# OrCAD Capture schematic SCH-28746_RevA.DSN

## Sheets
1 TITLE PAGE: title: USB-KW019032; rev: A; company: Freescale Semiconductor; note: SCH-28746 PDF: SPF-28746; note: 6501 William Cannon Drive West; note: Austin, TX 78735-8598
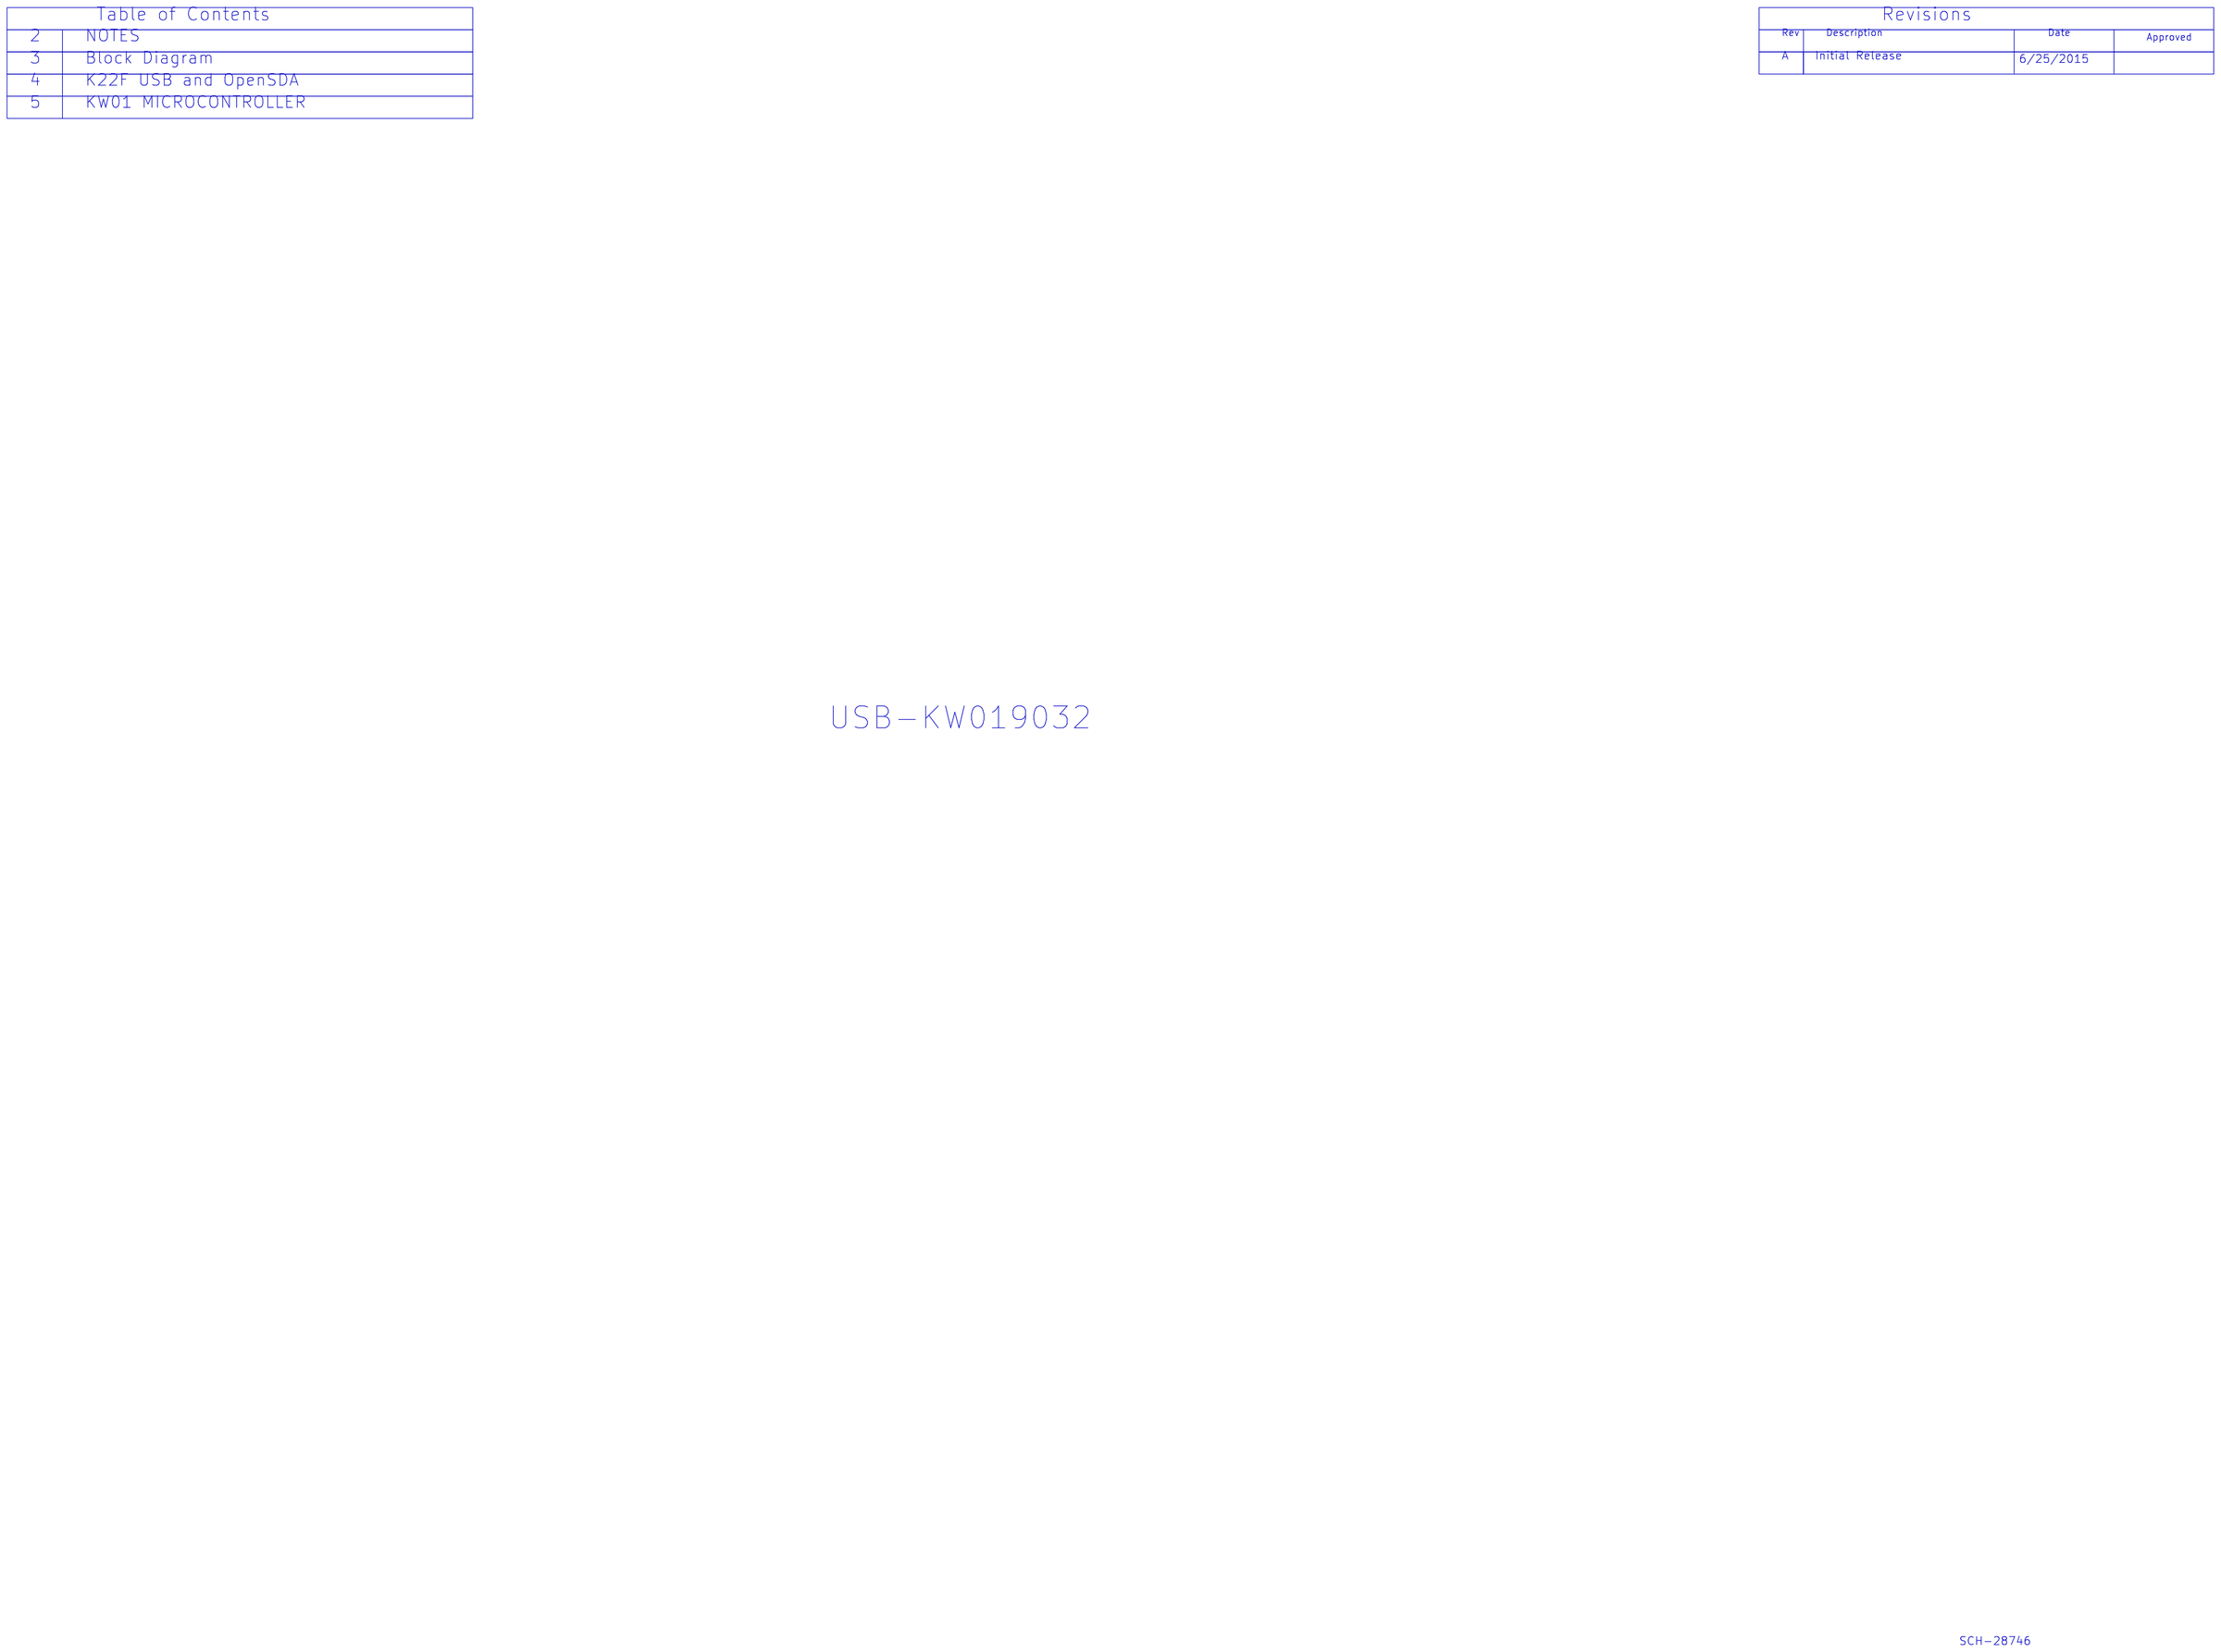
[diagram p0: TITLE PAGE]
2 NOTES
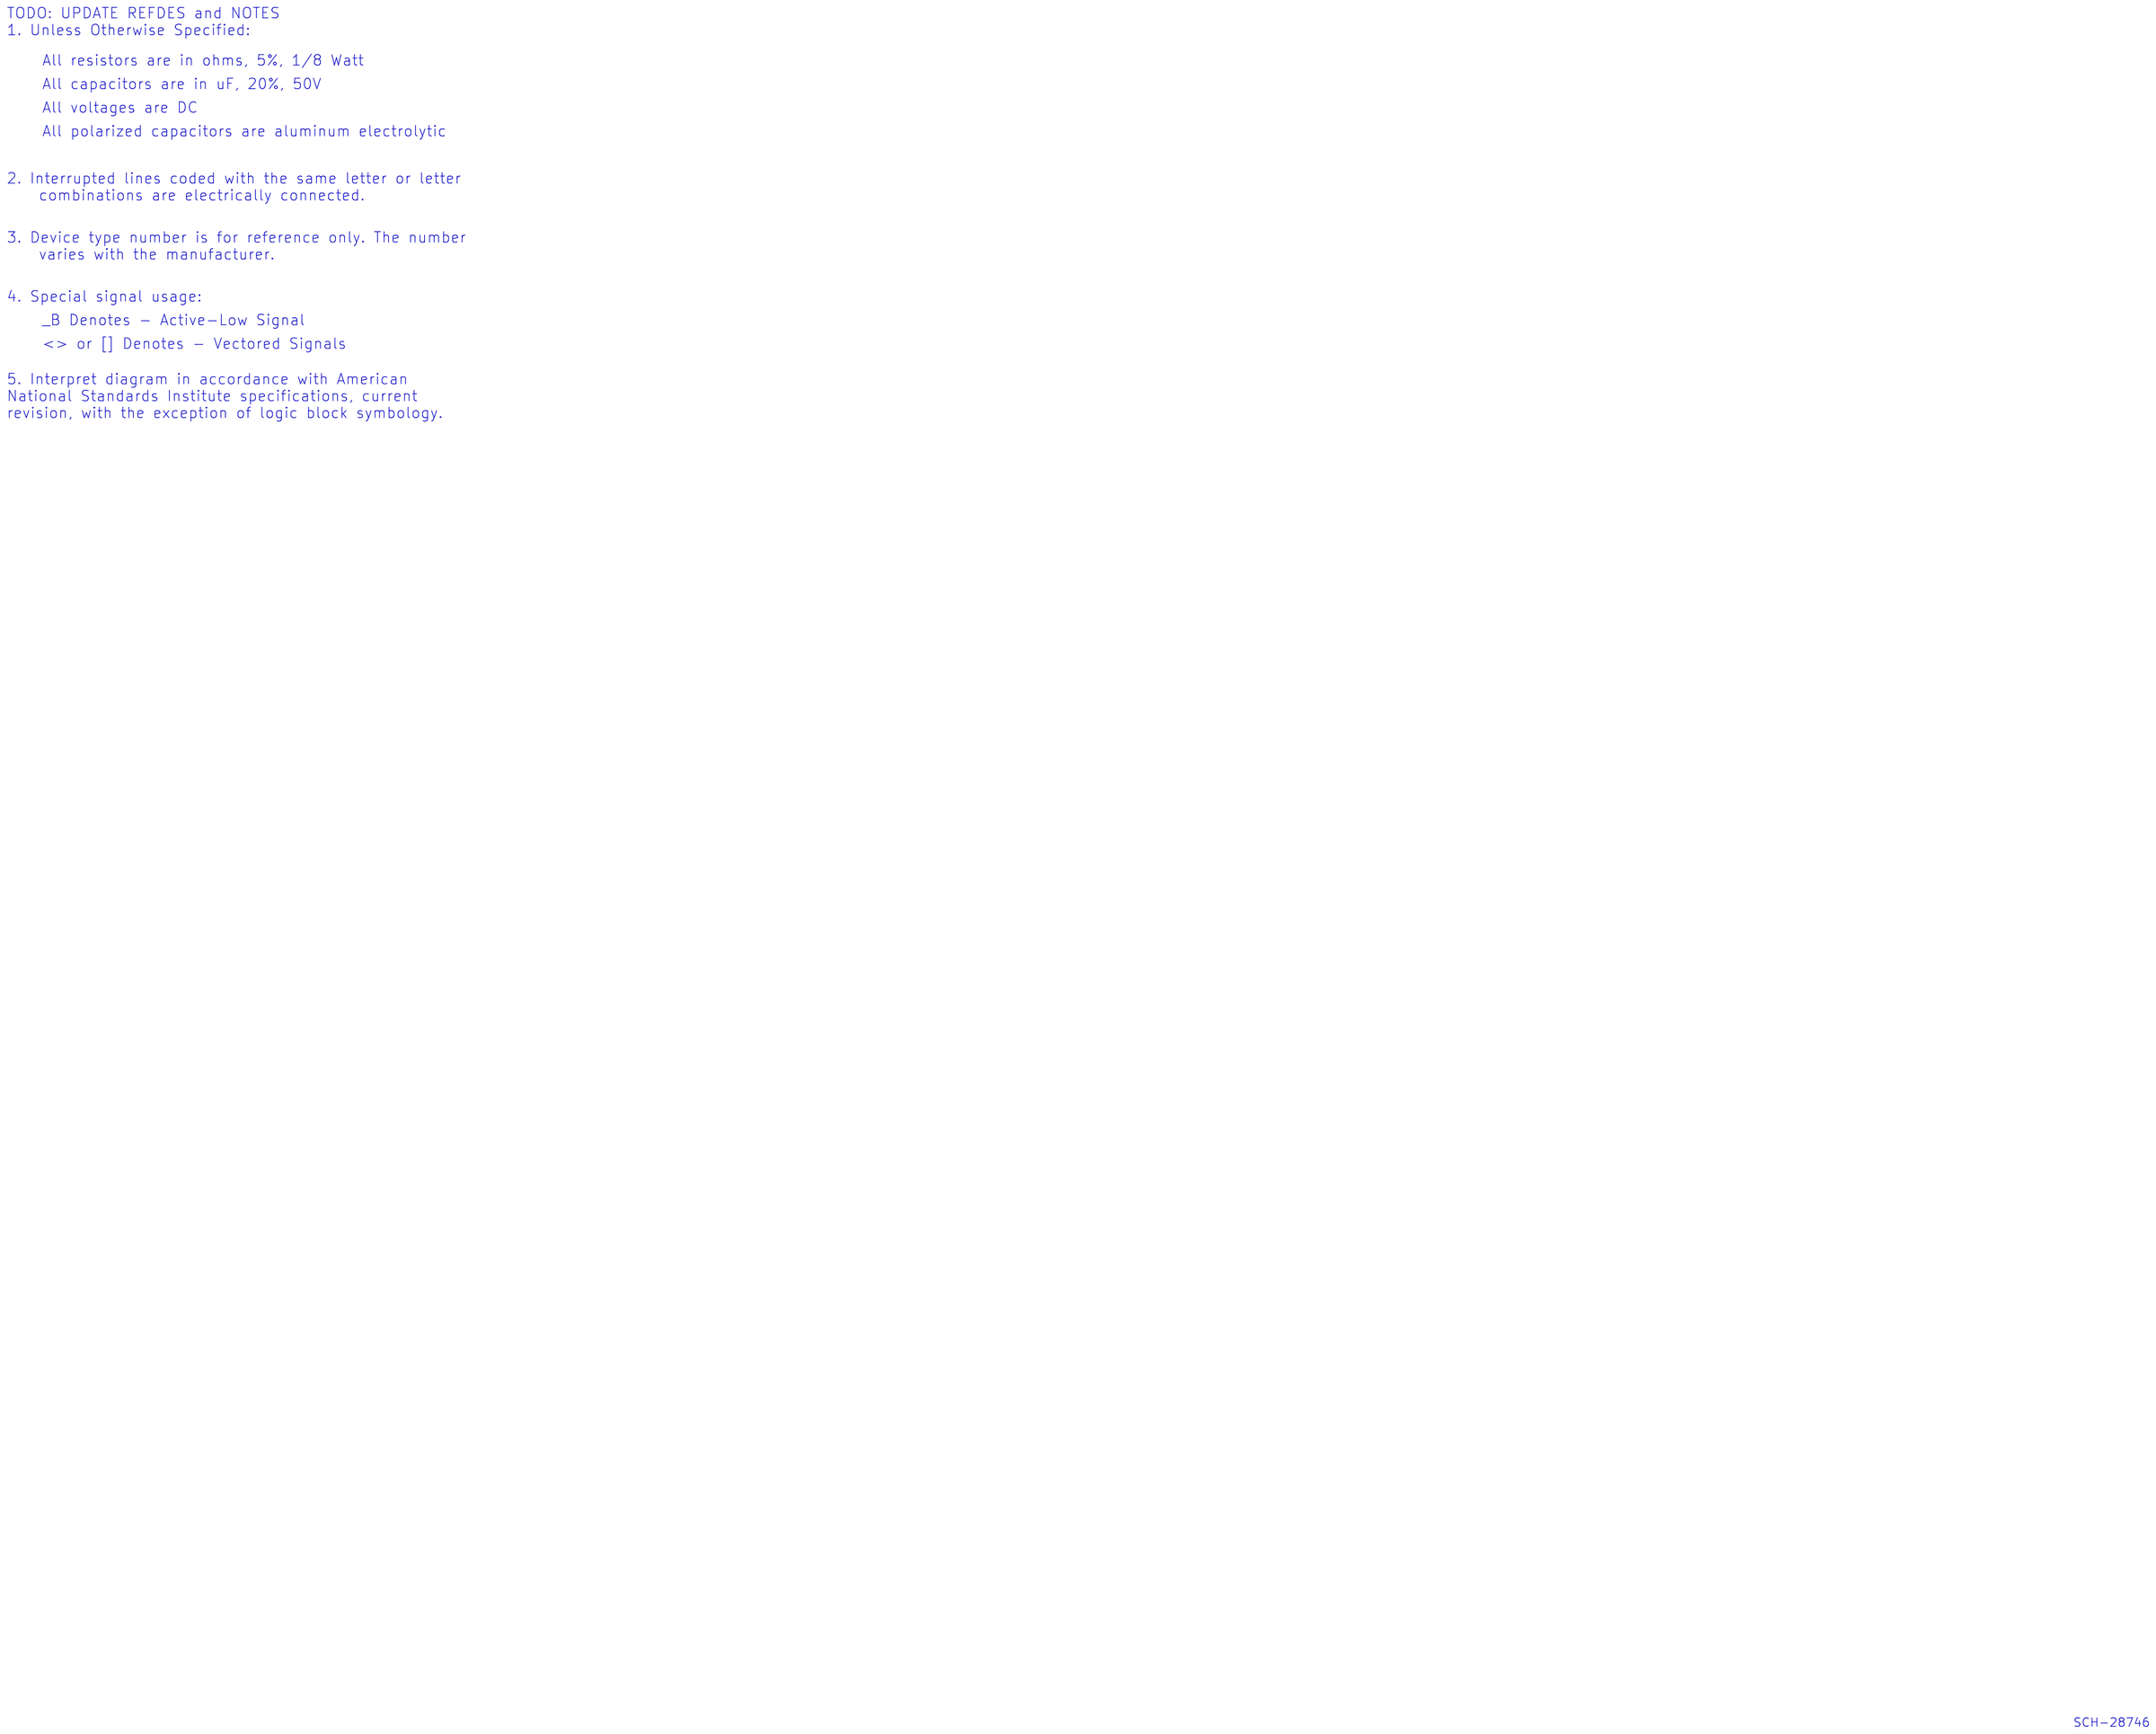
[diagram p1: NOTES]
3 BLOCK DIAGRAM
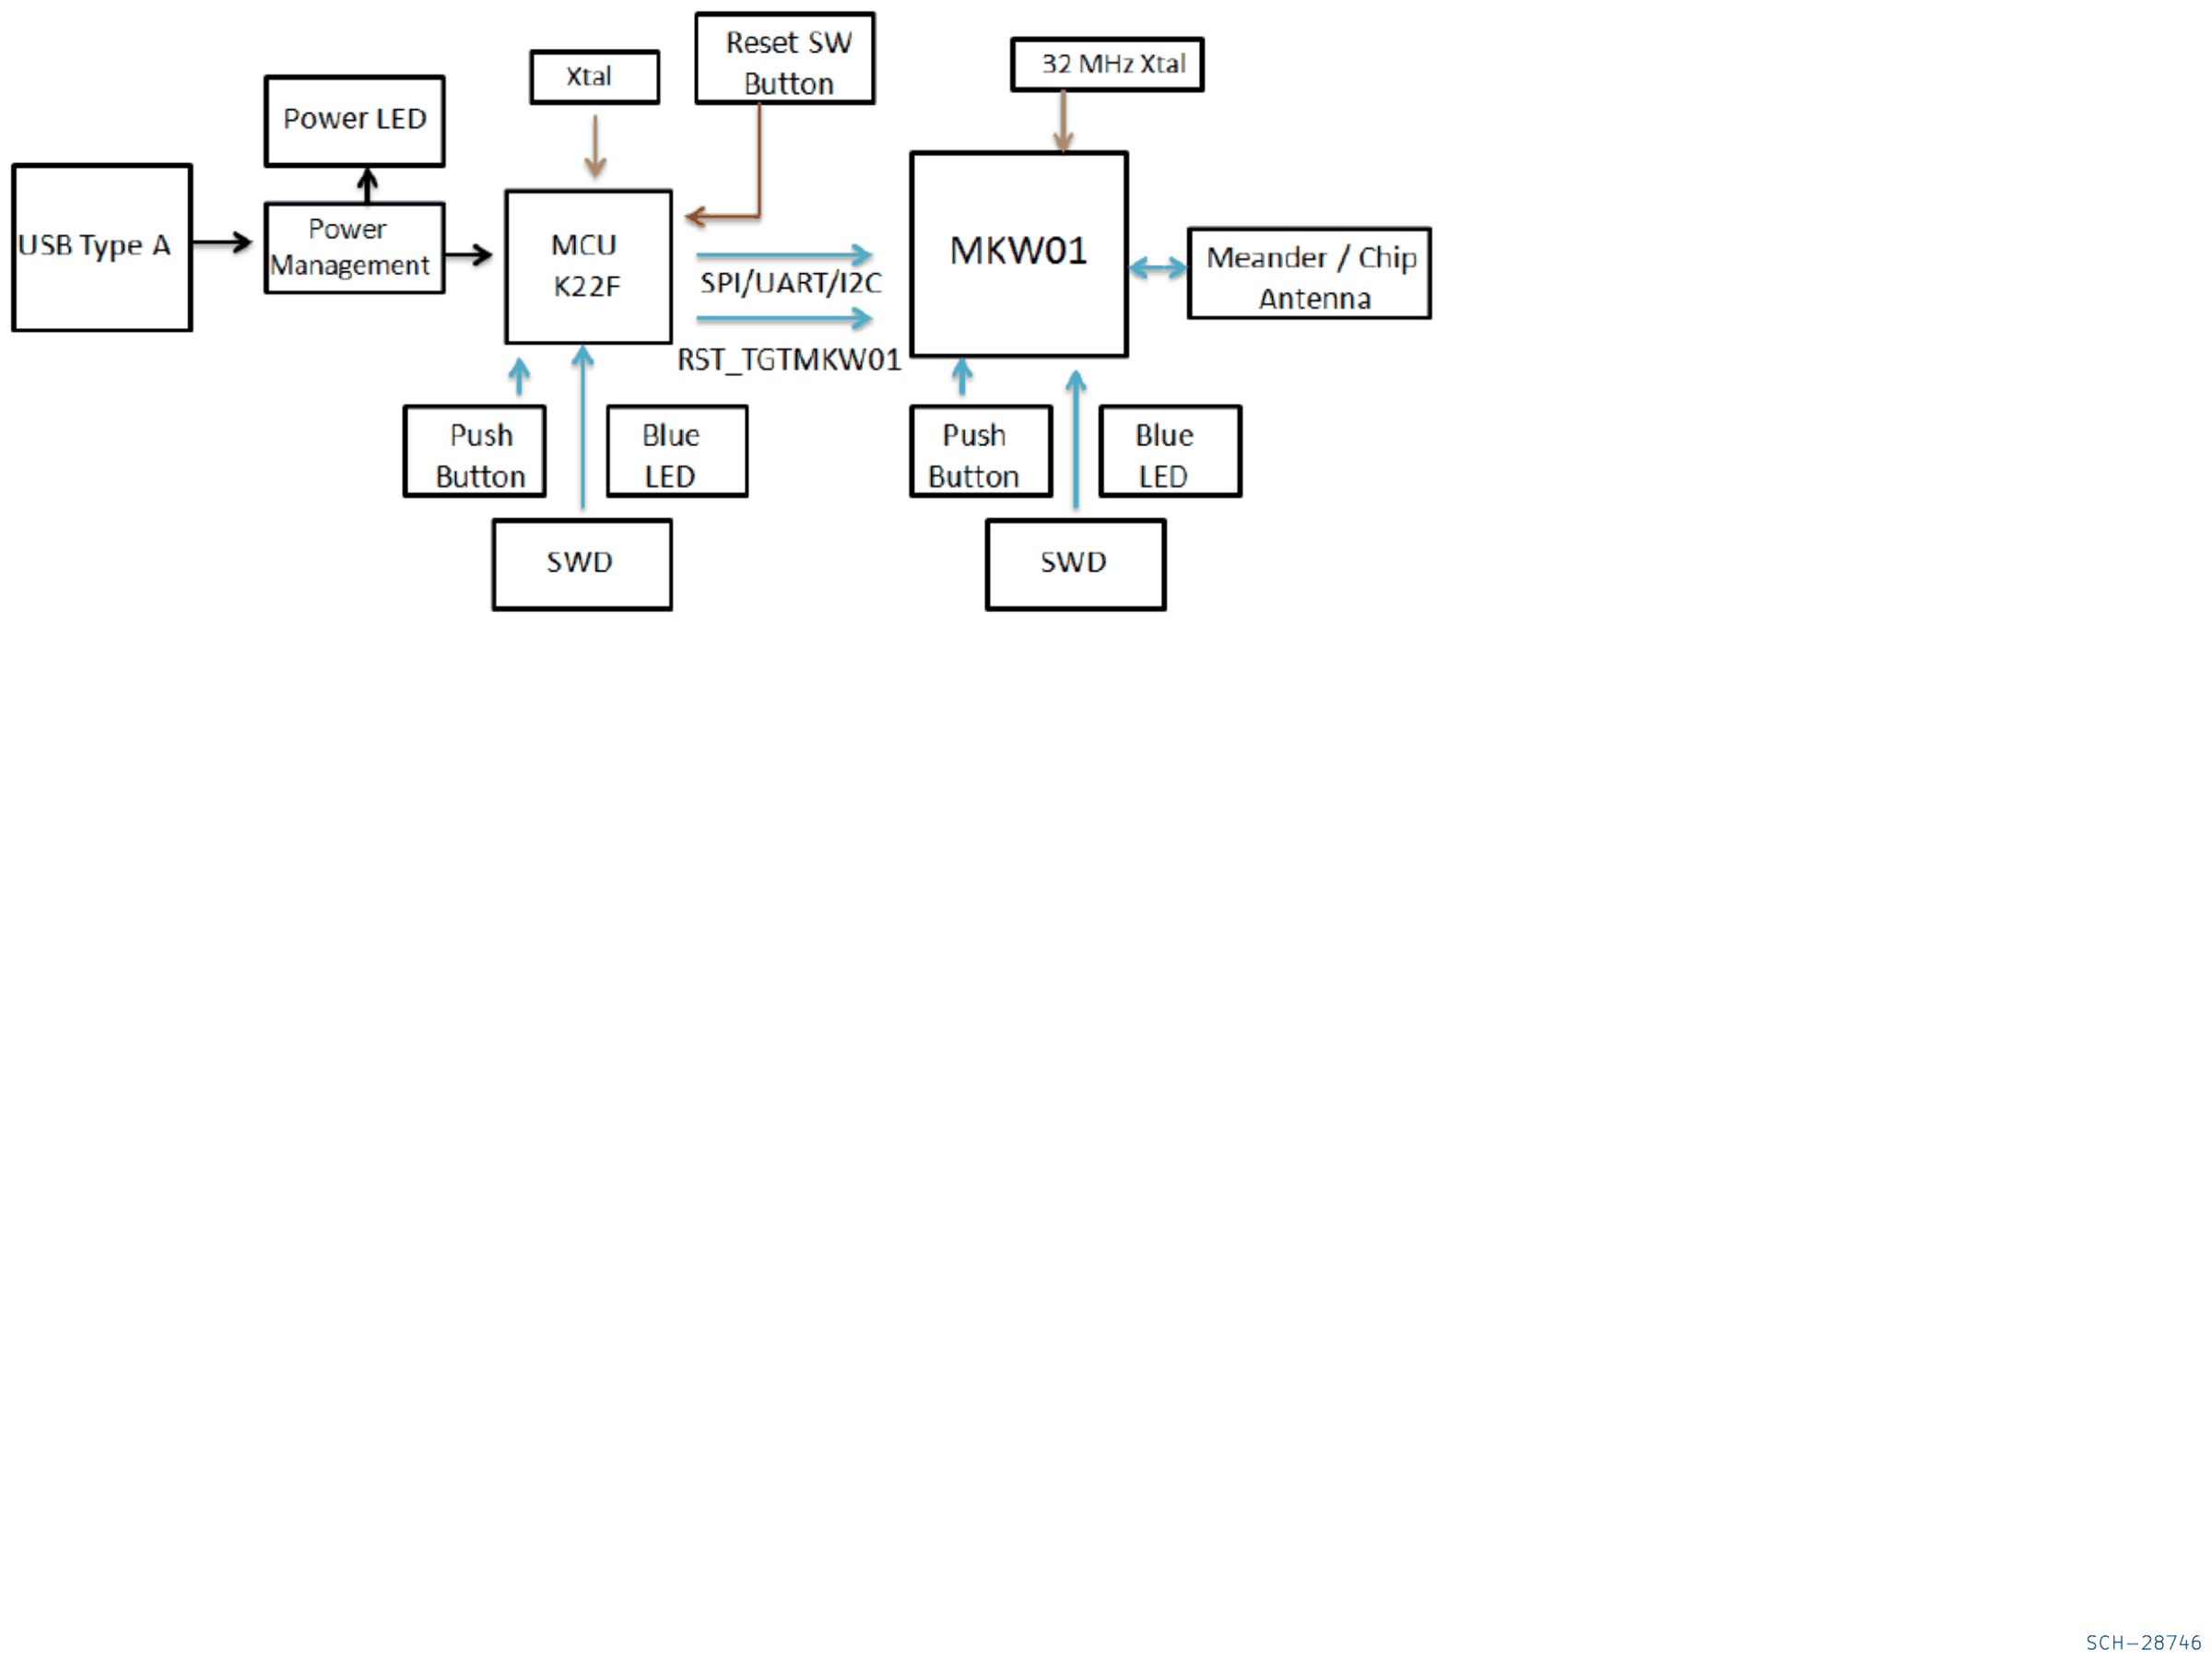
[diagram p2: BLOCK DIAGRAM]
4 USB and OpenSDA: size C
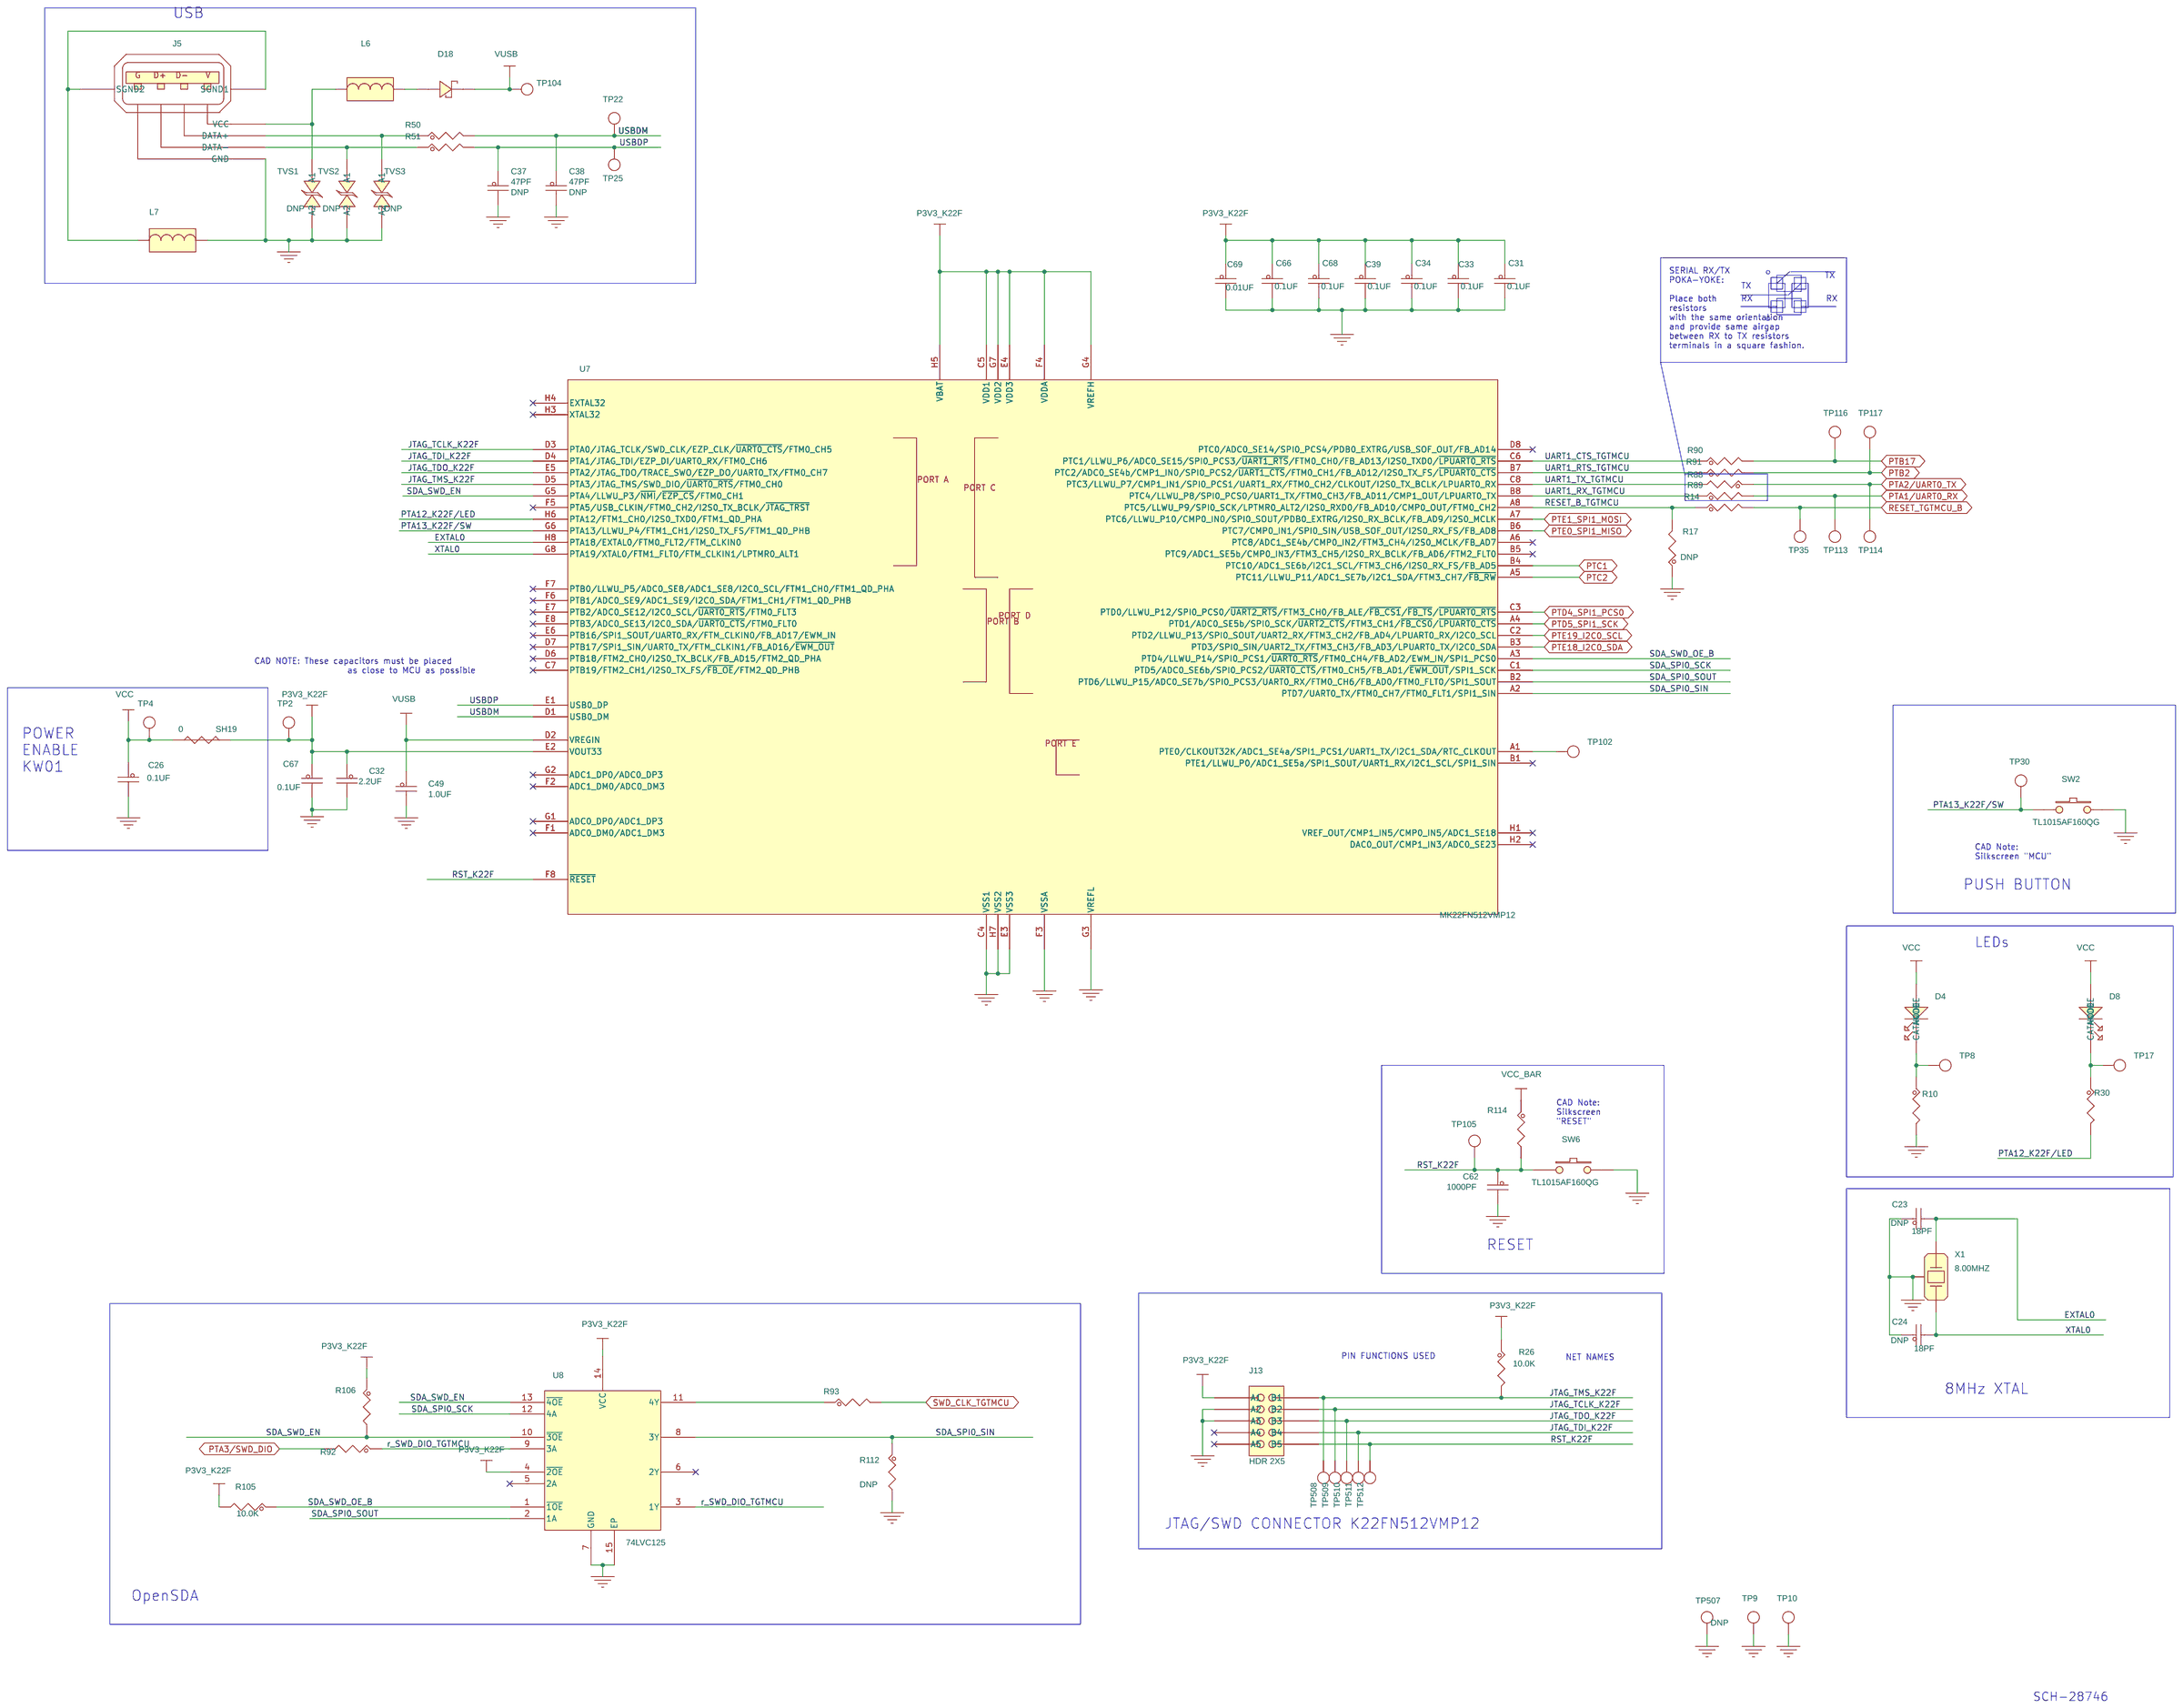
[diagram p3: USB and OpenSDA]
5 MICROCONTROLLER: size C
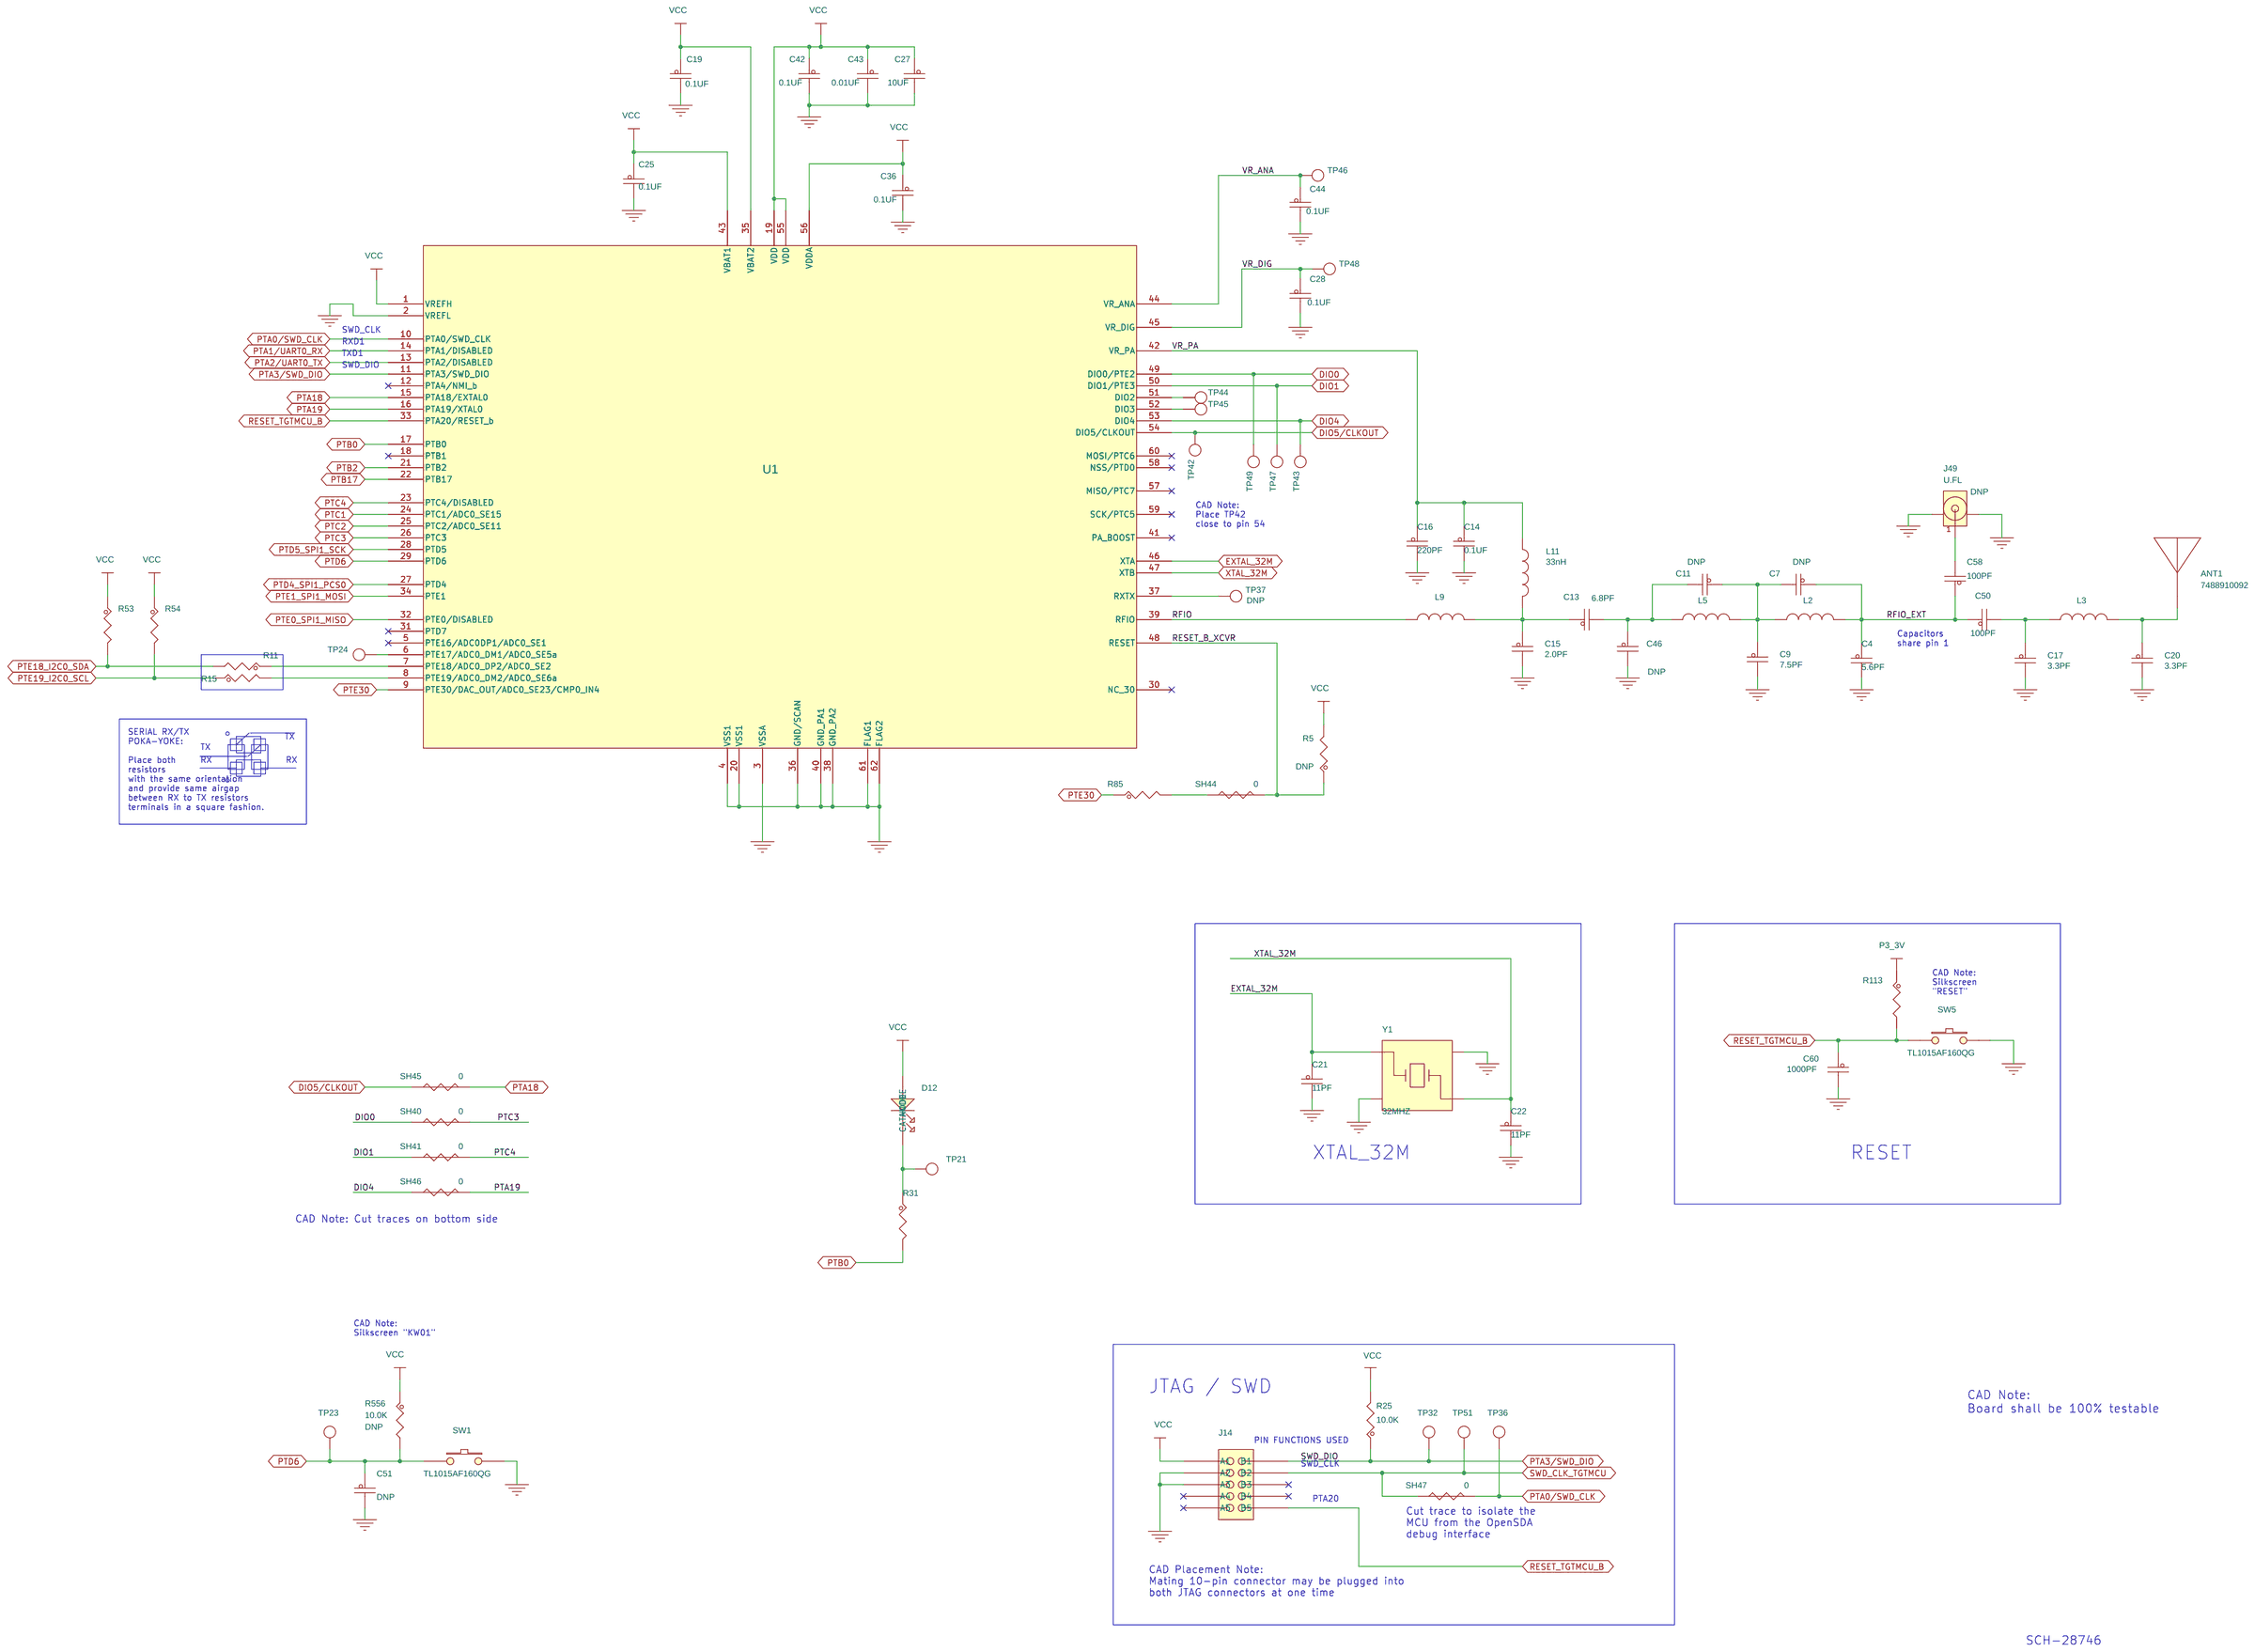
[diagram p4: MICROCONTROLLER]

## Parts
sheet MICROCONTROLLER
ANT1  7488910092  [ANT_7488910092]
C4  5.6PF  [0402_CC]
C7  10PF  [0402_CC]
C9  7.5PF  [0402_CC]
C11  10PF  [0402_CC]
C13  6.8PF  [0402_CC]
C14  0.1UF  [CC0402_25]
C15  2.0PF  [0402_CC]
C16  220PF  [0402_CC]
C17  3.3PF  [0402_CC]
C19  0.1UF  [CC0402_25]
C20  3.3PF  [0402_CC]
C21  11PF  [CC0402_25]
C22  11PF  [CC0402_25]
C25  0.1UF  [CC0402_25]
C27  10UF  [CC0805_OV]
C28  0.1UF  [CC0402_25]
C36  0.1UF  [CC0402_25]
C42  0.1UF  [CC0402_25]
C43  0.01UF  [CC0402_25]
C44  0.1UF  [CC0402_25]
C46  10PF  [0402_CC]
C50  100PF  [0402_CC]
C51  1000PF  [CC0402_25]
C58  100PF  [0402_CC]
C60  1000PF  [CC0402_25]
D12  BLUE  [led2_2p34_2p1x1p25]
J14  HDR 2X5  [CON_2RH_10_50]
J49  U.FL  [UFL_CONN3]
L2  0.0068UH  [0402_CC]
L3  10NH  [0402_CC]
L5  0.0068UH  [0402_CC]
L9  0.0047UH  [0402_CC]
L11  33nH  [0402_CC]
R5  4.7K  [RC0402_25]
R11  0  [RC0402_25]
R15  0  [RC0402_25]
R25  10.0K  [RC0402_25]
R31  220  [RC0402_25]
R53  4.7K  [RC0402_25]
R54  4.7K  [RC0402_25]
R85  100  [RC0402_25]
R113  15K  [RC0402_25]
R556  10.0K  [RC0402_25]
SH40  0  [RC0402_25_CT]
SH41  0  [RC0402_25_CT]
SH44  0  [RC0402_25_CT]
SH45  0  [RC0402_25_CT]
SH46  0  [RC0402_25_CT]
SH47  0  [RC0402_25_CT]
SW1  TL1015AF160QG  [TL1015AF160QG_2P]
SW5  TL1015AF160QG  [TL1015AF160QG_2P]
TP21  TPAD_030  [TPAD_030]
TP23  TPAD_030  [TPAD_030]
TP24  TPAD_030  [TPAD_030]
TP32  TPAD_030  [TPAD_030]
TP36  TPAD_030  [TPAD_030]
TP37  TESTLOOP_BLACK  [tp_th_063]
TP42  TPAD_030  [TPAD_030]
TP43  TPAD_030  [TPAD_030]
TP44  TPAD_030  [TPAD_030]
TP45  TPAD_030  [TPAD_030]
TP46  TPAD_040  [TPAD_040]
TP47  TPAD_030  [TPAD_030]
TP48  TPAD_040  [TPAD_040]
TP49  TPAD_030  [TPAD_030]
TP51  TPAD_030  [TPAD_030]
U1  MKW01Z128  [LGA60_0P5_8X8]
Y1  32MHZ  [xtlosc4_3p2x2p5mm_sm]
sheet USB and OpenSDA
C23  18PF  [CC0402_25]
C24  18PF  [CC0402_25]
C26  0.1UF  [CC0402_25]
C31  0.1UF  [CC0402_25]
C32  2.2UF  [CC0402_25]
C33  0.1UF  [CC0402_25]
C34  0.1UF  [CC0402_25]
C37  47PF  [CC0402_25]
C38  47PF  [CC0402_25]
C39  0.1UF  [CC0402_25]
C49  1.0UF  [CC0402_25]
C62  1000PF  [CC0402_25]
C66  0.1UF  [CC0402_25]
C67  0.1UF  [CC0402_25]
C68  0.1UF  [CC0402_25]
C69  0.01UF  [CC0402_25]
D4  GREEN  [LED_0603]
D8  BLUE  [led2_2p34_2p1x1p25]
D18  MSS1P3L  [smb_2p7x1p4]
J5  USB_TYPE_A  [MOLEX_480371000_USB_AM_SM]
J13  HDR 2X5  [CON_2RH_10_50]
L6  330 OHM  [IND_0805]
L7  330 OHM  [IND_0805]
R10  220  [RC0402_25]
R14  0  [RC0402_25]
R17  0  [RC0402_25]
R26  10.0K  [RC0402_25]
R30  220  [RC0402_25]
R50  33  [RC0402_25]
R51  33  [RC0402_25]
R88  1.0K  [RC0402_25]
R89  1.0K  [RC0402_25]
R90  1.0K  [RC0402_25]
R91  1.0K  [RC0402_25]
R92  1.0K  [RC0402_25]
R93  1.0K  [RC0402_25]
R105  10.0K  [RC0402_25]
R106  27K  [RC0402_25]
R112  27K  [RC0402_25]
R114  15K  [RC0402_25]
SH19  0  [RC0603_OV_CT]
SW2  TL1015AF160QG  [TL1015AF160QG_2P]
SW6  TL1015AF160QG  [TL1015AF160QG_2P]
TP2  TPAD_040  [TPAD_040]
TP4  TPAD_040  [TPAD_040]
TP8  TPAD_030  [TPAD_030]
TP9  TPAD_040  [TPAD_040]
TP10  TPAD_040  [TPAD_040]
TP17  TPAD_030  [TPAD_030]
TP22  TPAD_030  [TPAD_030]
TP25  TPAD_030  [TPAD_030]
TP30  TPAD_030  [TPAD_030]
TP35  TPAD_030  [TPAD_030]
TP102  TPAD_030  [TPAD_030]
TP104  TPAD_040  [TPAD_040]
TP105  TPAD_030  [TPAD_030]
TP113  TPAD_030  [TPAD_030]
TP114  TPAD_030  [TPAD_030]
TP116  TPAD_030  [TPAD_030]
TP117  TPAD_030  [TPAD_030]
TP507  TESTLOOP_BLACK  [tp_th_063]
TP508  TPAD_040  [TPAD_040]
TP509  TPAD_040  [TPAD_040]
TP510  TPAD_040  [TPAD_040]
TP511  TPAD_040  [TPAD_040]
TP512  TPAD_040  [TPAD_040]
TVS1  0402ESDA-MLP  [0402_mlp]
TVS2  0402ESDA-MLP  [0402_mlp]
TVS3  0402ESDA-MLP  [0402_mlp]
U7  MK22FN512VMP12  [MAPBGA64_0P5_5X5]
U8  74LVC125  [dqfn14_3x2p5mm]
X1  8.00MHZ  [xtal3_3p35x1p45_sm]

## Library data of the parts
ANT1 = ANT_Wurth_7488910092
C4 = CAP_NP: CAP CER 5.6PF 50V +/-0.25PF C0G CC0402; AGILE_PN: 150-75521; CAD_APPROVED: Yes; FPLIST: CC0402_25,CC0402_HD,0402_CC; HEIGHT: 0.55MM; MFG_NAME01: MURATA; MFG_PN01: GJM1555C1H5R6CB01D; ROHS: Yes; Tolerance: 0.25PF; VOLTAGE: 16V
C7 C11 C46 = CAP_NP: CAP CER 10PF 50V 5% C0G 0402; AGILE_PN: 150-75265; ASSY_OPT: DNP; CAD_APPROVED: YES; FPLIST: CC0402_25,CC0402_HD,0402_CC; HEIGHT: 0.635MM; MFG_NAME01: AVX; MFG_PN01: 04025A100JAT2A; ROHS: Yes; TOL: 5%; Tolerance: 5%; VOLTAGE: 50V
C9 = CAP_NP: CAP CER 7.5pF 50V +/-0.5pF C0G 0402; AGILE_PN: 150-79179; CAD_APPROVED: Yes; FPLIST: CC0402_25,CC0402_HD,0402_CC; HEIGHT: 0.55MM; MFG_NAME01: MURATA; MFG_PN01: GRM1555C1H7R5DA01D; ROHS: Yes; Tolerance: 0.5PF
C13 = CAP_NP: CAP CER 6.8PF 50V 0.5PF C0G 0402; AGILE_PN: 150-30300; CAD_APPROVED: Yes; FPLIST: CC0402_25,CC0402_HD,0402_CC; HEIGHT: 0.55MM; MFG_NAME01: MURATA; MFG_PN01: GRM1555C1H6R8DZ01J; ROHS: Yes; Tolerance: 0.5PF %; VOLTAGE: 50V
C14 C19 C25 C28 C36 C42 C44 = CAP_NP: CAP CER 0.1UF 16V 10% X7R 0402; AGILE_PN: 150-75182; CAD_APPROVED: Yes; FPLIST: CC0402_25,CC0402_HD,0402_CC; HEIGHT: 0.635MM; MFG_NAME01: KEMET; MFG_PN01: C0402C104K4RAC; ROHS: Yes; Tolerance: 10%; VOLTAGE: 16V
C15 = CAP_NP: CAP CER 2PF 50V 0.25PF C0G 0402; AGILE_PN: 150-77501; CAD_APPROVED: Yes; FPLIST: CC0402_25,CC0402_HD,0402_CC; HEIGHT: 0.55 MM; MFG_NAME01: MURATA; MFG_PN01: GRM1555C1H2R0CA01B; ROHS: Yes; Tolerance: 0.25PF; VOLTAGE: 50V
C16 = CAP_NP: CAP CER 220PF 50V 5% C0G 0402; AGILE_PN: 150-30297; CAD_APPROVED: Yes; FPLIST: CC0402_25,CC0402_HD,0402_CC; HEIGHT: 0.55MM; MFG_NAME01: KEMET; MFG_PN01: C0402C221J5GAC; ROHS: Yes; Tolerance: 5%; VOLTAGE: 50V
C17 C20 = CAP_NP: CAP CER 3.3PF 25V 0.1PF -- 0402; AGILE_PN: 150-78484; CAD_APPROVED: Yes; FPLIST: CC0402_25,CC0402_HD,0402_CC; HEIGHT: 0.5MM; MFG_NAME01: AVX; MFG_PN01: 04023J3R3BBSTR; ROHS: Yes; VOLTAGE: 25V
C21 C22 = CAP_NP: CAP CER 11PF 50V 1% C0G 0402; CAD_APPROVED: Yes; FPLIST: CC0402_25,CC0402_HD,0402_CC; HEIGHT: 0.55MM; MFG_NAME01: KEMET; MFG_PN01: CBR04C110F5GAC; ROHS: Yes; Tolerance: 5%; VOLTAGE: 50V
C27 = CAP_NP: CAP CER 10UF 10V 10% X5R 0805; CAD_APPROVED: Yes; FPLIST: CC0805_OV,CC0805,0805_CC; HEIGHT: 1.6MM; MFG_NAME01: MURATA; MFG_PN01: GRM21BR71A106KE51L; ROHS: Yes; Tolerance: 10%; VOLTAGE: 10V
C43 = CAP_NP: CAP CER 0.01UF 50V 10% X7R 0402; FPLIST: CC0402_25,CC0402_HD,0402_CC; HEIGHT: 0.74 MM; MFG_NAME01: KEMET; MFG_PN01: C0402C103K5RAC; ROHS: Yes; Tolerance: 10%; VOLTAGE: 50V
C50 C58 = CAP_NP: CAP CER 100PF 50V 5% C0G 0402; AGILE_PN: 150-30247; CAD_APPROVED: Yes; FPLIST: CC0402_25,CC0402_HD,0402_CC; HEIGHT: 0.55MM; MFG_NAME01: KEMET; MFG_PN01: C0402C101J5GAC; ROHS: Yes; Tolerance: 5%; VOLTAGE: 50V
C51 = CAP_NP: CAP CER 1000PF 50V 5% C0G 0402; AGILE_PN: 150-76334; ASSY_OPT: DNP; CAD_APPROVED: Yes; FPLIST: CC0402_25,CC0402_HD,0402_CC; HEIGHT: 0.55MM; MFG_NAME01: MURATA; MFG_PN01: GRM1555C1H102JA01D; ROHS: Yes; Tolerance: 5%; VOLTAGE: 50V
C60 C62 = CAP_NP: CAP CER 1000PF 50V 5% C0G 0402; AGILE_PN: 150-76334; CAD_APPROVED: Yes; FPLIST: CC0402_25,CC0402_HD,0402_CC; HEIGHT: 0.55MM; MFG_NAME01: MURATA; MFG_PN01: GRM1555C1H102JA01D; ROHS: Yes; Tolerance: 5%; VOLTAGE: 50V
D8 D12 = LED: LED BLUE SGL 20MA SMT 0805; AGILE_PN: 370-76451; CAD_APPROVED: Yes; HEIGHT: 0.9MM; MFG_NAME01: LITE ON; MFG_PN01: LTST-C171TBKT; ROHS: Yes
J14 = CONN_HDR_5X2: CONN,HEAD,2X5,STR,50/50 CON-2RH-10-50; AGILE_PN: 210-07961-00; CAD_APPROVED: Yes; HEIGHT: 3.91 MM; MFG_NAME01: SAMTEC; MFG_PN01: FTS-105-01-F-D; ROHS: Yes
J49 = UFL_CONN: CON, U.FL, VERT 1.25MM, 50 OHM MALE PIN 6GHZ; ASSY_OPT: DNP; MFG_NAME01: HIROSE; MFG_PN01: U.FL-R-SMT-1; ROHS: Yes
L2 L5 = INDUCTOR: IND -- 0.0068UH@100MHZ 300MA 5% 0402; AGILE_PN: 180-30075; CAD_APPROVED: Yes; FPLIST: IND_0402,0402_CC; HEIGHT: 0.55mm; MFG_NAME01: MURATA; MFG_PN01: LQG15HS6N8J02D; ROHS: Yes
L3 = INDUCTOR: IND -- 0.010UH@100MHZ 300MA 5% 0402; FPLIST: IND_0402,0402_CC; HEIGHT: 0.55mm; MFG_NAME01: MURATA; MFG_PN01: LQG15HS10NJ02D; ROHS: Yes
L9 = INDUCTOR: IND -- 0.0047UH@100MHZ 300MA +/-0.3NF 0402; AGILE_PN: 180-30074; CAD_APPROVED: Yes; FPLIST: IND_0402,0402_CC; HEIGHT: 0.55mm; MFG_NAME01: MURATA; MFG_PN01: LQG15HS4N7S02D; ROHS: Yes
L11 = INDUCTOR: IND -- 0.033UH@100MHZ 200MA 5% 0402; AGILE_PN: 180-75099; CAD_APPROVED: YES; FPLIST: IND_0402,0402_CC; HEIGHT: 0.55MM; MFG_NAME01: MURATA; MFG_PN01: LQG15HS33NJ02D; ROHS: Yes; Tolerance: 5%
R5 = RES: RES MF 4.7K 1/16W 5% 0402; ASSY_OPT: DNP; FPLIST: RC0402_25,RC0402_HD,RC0402_X2,0402_CC; MFG_NAME01: YAGEO AMERICA; MFG_PN01: RC0402JR-134K7L; ROHS: Yes; Tolerance: 5%
R11 R15 = RES: RES MF ZERO OHM 1/16W 5% 0402; FPLIST: RC0402_25,RC0402_HD,RC0402_X2,0402_CC; MFG_NAME01: VISHAY INTERTECHNOLOGY; MFG_PN01: CRCW04020000Z0ED; ROHS: Yes; Tolerance: 5%
R25 = RES: RES MF 10.0K 1/16W 1% AEC-Q200 0402; AGILE_PN: 470-75416; CAD_APPROVED: Yes; FPLIST: RC0402_25,RC0402_HD,0402_CC; HEIGHT: 0.4MM; MFG_NAME01: VISHAY INTERTECHNOLOGY; MFG_PN01: CRCW040210K0FKED; ROHS: Yes; TOL: 1%; Tolerance: 1%
R10 R30 R31 = RES: RES MF 220 OHM 1/16W 5% 0402; CAD_APPROVED: Yes; FPLIST: RC0402_25,RC0402_HD,0402_CC; MFG_NAME01: VISHAY INTERTECHNOLOGY; MFG_PN01: CRCW0402220RJNED; ROHS: Yes; Tolerance: 5%
R53 R54 = RES: RES MF 4.7K 1/16W 5% 0402; FPLIST: RC0402_25,RC0402_HD,RC0402_X2,0402_CC; MFG_NAME01: YAGEO AMERICA; MFG_PN01: RC0402JR-134K7L; ROHS: Yes; Tolerance: 5%
R85 = RES: RES MF 100 OHM 1/16W 5% 0402; CAD_APPROVED: Yes; FPLIST: RC0402_25,RC0402_HD,RC0402_X2,0402_CC; MFG_NAME01: VISHAY INTERTECHNOLOGY; MFG_PN01: CRCW0402100RJNED; ROHS: Yes; Tolerance: 5%
R113 R114 = RES: RES MF 15.0K 1/16W 1% 0402; CAD_APPROVED: Yes; FPLIST: RC0402_25,RC0402_HD,0402_CC; HEIGHT: 0.4 MM; MFG_NAME01: BOURNS; MFG_PN01: CR0402-FX-1502GLF; ROHS: Yes; TOL: 1%; Tolerance: 1%
R556 = RES: RES MF 10.0K 1/16W 1% AEC-Q200 0402; AGILE_PN: 470-75416; ASSY_OPT: DNP; CAD_APPROVED: Yes; FPLIST: RC0402_25,RC0402_HD,0402_CC; HEIGHT: 0.4MM; MFG_NAME01: VISHAY INTERTECHNOLOGY; MFG_PN01: CRCW040210K0FKED; ROHS: Yes; SIGNAL_MODEL: DEFAULT_RESISTOR_10000OHM_2_1; TOL: 1%; Tolerance: 1%
SH40 SH41 SH44-SH47 = SH_RES: CUT TRACE RESISTOR; FPLIST: RC0402_25_CT,RC0402_HD_CT,0402_CC_CT
SW1 SW2 SW5 SW6 = SW_TACT-SPST-2_SMD
TP8 TP17 TP21-TP25 TP30 TP32 TP35 TP36 TP42-TP45 TP47 TP49 TP51 TP102 TP113 TP114 TP116 TP117 = TESTLOOP: TEST POINT PAD 30MIL DIA SMT, NO PART TO ORDER; AGILE_PN: 211-76642; CAD_APPROVED: Yes; HEIGHT: 0.1MM; MFG_NAME01: NOTACOMPONENT; MFG_PN01: NOTACOMPONENT; ROHS: Yes
TP37 TP507 = TestLoop: TEST POINT PC MULTI PURPOSE BLK TH; AGILE_PN: 210-79450; ASSY_OPT: DNP; CAD_APPROVED: Yes; HEIGHT: 8.13MM; MFG_NAME01: KEYSTONE ELECTRONICS; MFG_PN01: 5011; ROHS: Yes
TP2 TP4 TP9 TP10 TP46 TP48 TP104 TP508-TP512 = TestLoop: TEST POINT PAD 40MIL DIA SMT, NO PART TO ORDER; AGILE_PN: 211-76643; CAD_APPROVED: Yes; HEIGHT: 0.1MM; MFG_NAME01: NOTACOMPONENT; MFG_PN01: NOTACOMPONENT; ROHS: Yes
U1 = MKW01Z128_LGA_0: IC MCU ARM 48MHZ 128KB FLASH 16KB RAM 1.8-3.6V LGA60; AGILE_PN: TMP-WF-17753; CAD_APPROVED: Yes; HEIGHT: 0.98MM; MFG_NAME01: FREESCALE SEMICONDUCTOR; MFG_PN01: MKW01Z128CHN; PRE_APN: 344-01481; ROHS: Yes
Y1 = XTAL_13Y: XTAL 32MHZ 9PF -- SMT 3.2X2.5MM; AGILE_PN: 230-77690; CAD_APPROVED: Yes; HEIGHT: 0.8MM; MFG_NAME01: NDK; MFG_PN01: EXS00A-CS02368; ROHS: Yes
C23 C24 = CAP_NP: CAP CER 18PF 50V 5% C0G 0402; AGILE_PN: 150-75658; ASSY_OPT: DNP; CAD_APPROVED: Yes; FPLIST: CC0402_25,CC0402_HD,0402_CC; HEIGHT: 0.55MM; MFG_NAME01: KEMET; MFG_PN01: C0402C180J5GAC; ROHS: Yes; Tolerance: 5%; VOLTAGE: 50V
C26 = CAP_NP: CAP CER 0.1UF 10V 10% X5R 0402; AGILE_PN: 150-75634; CAD_APPROVED: Yes; FPLIST: CC0402_25,CC0402_HD,0402_CC; HEIGHT: 0.64MM; MFG_NAME01: KEMET; MFG_PN01: C0402C104K8PAC; ROHS: Yes; TOL: 10%; Tolerance: 10%; VOLTAGE: 10V
C31 C33 C34 C39 C66-C68 = CAP_NP: CAP CER 0.1UF 10V 10% X5R 0402; AGILE_PN: 150-75634; CAD_APPROVED: Yes; FPLIST: CC0402_25,CC0402_HD,0402_CC; HEIGHT: 0.64MM; MFG_NAME01: KEMET; MFG_PN01: C0402C104K8PAC; PRIORITY_PN: 021-00169; ROHS: Yes; TOL: 10%; Tolerance: 10%; VOLTAGE: 10V
C32 = CAP_NP: CAP CER 2.2UF 6.3V 20% X5R 0402; AGILE_PN: 150-76792; CAD_APPROVED: Yes; FPLIST: CC0402_25,CC0402_HD,0402_CC; HEIGHT: 0.55MM; MFG_NAME01: KEMET; MFG_PN01: C0402C225M9PACTU; ROHS: Yes; Tolerance: 20%; VOLTAGE: 6.3V
C37 C38 = CAP_NP: CAP CER 47PF 50V 5% C0G 0402; ASSY_OPT: DNP; CAD_APPROVED: YES; FPLIST: CC0402_25,CC0402_HD,0402_CC; HEIGHT: 0.56MM; MFG_NAME01: MURATA; MFG_PN01: GRM1555C1H470JA01D; ROHS: Yes; TOL: 5%; Tolerance: 5%; VOLTAGE: 16V
C49 = CAP_NP: CAP CER 1.0UF 10V 10% X5R 0402; AGILE_PN: 150-75772; CAD_APPROVED: Yes; FPLIST: CC0402_25,CC0402_HD,0402_CC; HEIGHT: 0.6MM; MFG_NAME01: YAGEO AMERICA; MFG_PN01: CC0402KRX5R6BB105; ROHS: Yes; VOLTAGE: 10V
C69 = CAP_NP: CAP CER 0.01UF 16V 20% X7R 0402; AGILE_PN: 150-30082; CAD_APPROVED: Yes; FPLIST: CC0402_25,CC0402_HD,0402_CC; HEIGHT: 0.56MM; MFG_NAME01: AVX; MFG_PN01: 0402YC103MAT2A; ROHS: Yes; TOL: 20%; Tolerance: 20%; VOLTAGE: 16V
D4 = LED: LED GRN SGL 20MA 0603; AGILE_PN: 370-76565; CAD_APPROVED: Yes; HEIGHT: 0.67MM; MFG_NAME01: OSRAM; MFG_PN01: LG L29K-G2J1-24-Z; ROHS: Yes
D18 = DIODE_SCHTKY: DIODE SCH 1A 20V MICROSMP SMT; AGILE_PN: 480-76978; CAD_APPROVED: Yes; HEIGHT: 0.73MM; MFG_NAME01: VISHAY INTERTECHNOLOGY; MFG_PN01: MSS1P3L-M3/89A; ROHS: Yes
J5 = USB_A: CON 1X4 USB_TYPE_A_MALE RA SMT -- 178H AU; CAD_APPROVED: Yes; HEIGHT: 4.6MM; MFG_NAME01: MOLEX; MFG_PN01: 480371000; ROHS: Yes
J13 = CONN_HDR_5X2: HDR 2X5 TH 50MIL CTR 254H AU 91L; AGILE_PN: 210-80440; CAD_APPROVED: Yes; HEIGHT: 6.45MM; MFG_NAME01: SAMTEC; MFG_PN01: FTSH-105-04-F-D; ROHS: Yes
L6 L7 = BEAD: IND FER BEAD 330OHM@100MHZ 2.5A -- SMT; AGILE_PN: 180-30021; CAD_APPROVED: YES; HEIGHT: 1.05 MM; MFG_NAME01: TDK; MFG_PN01: MPZ2012S331A; PART_TYPE: FERRITE; ROHS: Yes; Tolerance: 25%
R14 = RES: RES MF ZERO OHM 1/16W 5% 0402; CAD_APPROVED: Yes; FPLIST: RC0402_25,RC0402_HD,RC0402_X2,0402_CC; HEIGHT: 0.45 MM; MFG_NAME01: VISHAY INTERTECHNOLOGY; MFG_PN01: CRCW04020000Z0ED; PRIORITY_PN: 006-00559; ROHS: Yes; SIGNAL_MODEL: DEFAULT_RESISTOR_0.001OHM_2_1; TOL: 5%; Tolerance: 5%; VOLTAGE: 1/16W
R17 = RES: RES MF ZERO OHM 1/16W 5% 0402; ASSY_OPT: DNP; CAD_APPROVED: Yes; FPLIST: RC0402_25,RC0402_HD,RC0402_X2,0402_CC; HEIGHT: 0.45 MM; MFG_NAME01: VISHAY INTERTECHNOLOGY; MFG_PN01: CRCW04020000Z0ED; PRIORITY_PN: 006-00559; ROHS: Yes; SIGNAL_MODEL: DEFAULT_RESISTOR_0.001OHM_2_1; TOL: 5%; Tolerance: 5%; VOLTAGE: 1/16W
R26 R105 = RES: RES MF 10.0K 1/16W 1% AEC-Q200 0402; AGILE_PN: 470-75416; CAD_APPROVED: Yes; FPLIST: RC0402_25,RC0402_HD,0402_CC; HEIGHT: 0.4MM; MFG_NAME01: VISHAY INTERTECHNOLOGY; MFG_PN01: CRCW040210K0FKED; PRIORITY_PN: 006-00552; ROHS: Yes; TOL: 1%; Tolerance: 1%
R50 R51 = RES: RES MF 33.0 OHM 1/16W 1% 0402; FPLIST: RC0402_25,RC0402_HD,RC0402_X2,0402_CC; MFG_NAME01: VISHAY INTERTECHNOLOGY; MFG_PN01: CRCW040233R0FKED; ROHS: Yes; Tolerance: 1%
R88-R93 = RES: RES MF 1.0K 1/16W 1% 0402; AGILE_PN: 470-76037; CAD_APPROVED: Yes; FPLIST: RC0402_25,RC0402_HD,RC0402_X2,0402_CC; HEIGHT: 0.4MM; MFG_NAME01: YAGEO AMERICA; MFG_PN01: RC0402FR-071KL; ROHS: Yes; TOL: 1%; Tolerance: 1%
R106 = RES: RES MF 27K 1/16W 5% 0402; AGILE_PN: 470-76069; CAD_APPROVED: Yes; FPLIST: RC0402_25,RC0402_HD,0402_CC; MFG_NAME01: VISHAY INTERTECHNOLOGY; MFG_PN01: CRCW040227K0JNED; ROHS: Yes; Tolerance: 5%
R112 = RES: RES MF 27K 1/16W 5% 0402; AGILE_PN: 470-76069; ASSY_OPT: DNP; CAD_APPROVED: Yes; FPLIST: RC0402_25,RC0402_HD,0402_CC; MFG_NAME01: VISHAY INTERTECHNOLOGY; MFG_PN01: CRCW040227K0JNED; ROHS: Yes; Tolerance: 5%
SH19 = SH_RES: Cut Trace Resistor; FPLIST: RC0603_OV,RC0603,0603_CC; MFG_NAME01: NOTACOMPONENT; MFG_PN01: NOTACOMPONENT
TP105 = TestLoop: TEST POINT PAD 30MIL DIA SMT, NO PART TO ORDER; AGILE_PN: 211-76642; CAD_APPROVED: Yes; HEIGHT: 0.1MM; MFG_NAME01: NOTACOMPONENT; MFG_PN01: NOTACOMPONENT; ROHS: Yes
TVS1-TVS3 = DIODE_TVS_BIDIR: DIODE TVS BIDIR -- 30V 0402; AGILE_PN: 480-76179; ASSY_OPT: DNP; CAD_APPROVED: Yes; HEIGHT: 0.44MM; MFG_NAME01: COOPER BUSSMANN; MFG_PN01: 0402ESDA-MLP1; ROHS: Yes
U7 = MK22FN512_BGA_64P: IC MCU 32BIT 512KB FLASH 128KB RAM 1.71-3.6V 120MHZ MAPBGA 64; AGILE_PN: 344-02113; CAD_APPROVED: Yes; HEIGHT: 1.23 MM; MFG_NAME01: FREESCALE SEMICONDUCTOR; ROHS: Yes
U8 = 74LVC125_DHVQFN_14P: IC QUAD BUF LINE DRV TS 1.2-3.6V DHVQFN14; AGILE_PN: 312-80767; CAD_APPROVED: Yes; HEIGHT: 1MM; MFG_NAME01: NXP Semiconductors; MFG_PN01: 74LVC125ABQ,115; ROHS: Yes
X1 = XTAL_CS: XTAL 8.00MHZ RSN CERAMIC -- SMT; AGILE_PN: 230-77664; CAD_APPROVED: Yes; HEIGHT: 0.8MM; MFG_NAME01: MURATA; MFG_PN01: CSTCE8M00G55-R0; PRIORITY_PN: 048-00290; ROHS: Yes

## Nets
GND: C4.2 C9.2 C14.2 C15.2 C16.2 C17.2 C19.2 C20.2 C21.2 C22.2 C23.1 C24.1 C25.2 C26.2 C27.2 C28.2 C31.2 C32.2 C33.2 C34.2 C36.2 C37.2 C38.2 C39.2 C42.2 C43.2 C44.2 C46.2 C49.2 C51.2 C60.2 C62.2 C66.2 C67.2 C68.2 C69.2 J5.A4(GND) J13.3(A2) J13.5(A3) J14.3(A2) J14.5(A3) J49.2(SHIELD1) J49.3(SHIELD2) L7.2 R10.2 R17.1 R112.2 SW1.2 SW2.2 SW5.1 SW6.1 TP9.1(Pin1) TP10.1(Pin1) TP507.1(Pin1) TVS1.2(A2) TVS2.2(A2) TVS3.2(A2) U1.2(VREFL) U1.3(VSSA) U1.4(VSS1) U1.20(VSS1) U1.36(GND/SCAN) U1.38(GND_PA2) U1.40(GND_PA1) U1.61(FLAG1) U1.62(FLAG2) U7.C4(VSS1) U7.E3(VSS3) U7.F3(VSSA) U7.G3(VREFL) U7.H7(VSS2) U8.7(GND) U8.15(EP) X1.2 Y1.2 Y1.4
P3V3_K22F: C31.1 C32.1 C33.1 C34.1 C39.1 C66.1 C67.1 C68.1 C69.1 J13.1(A1) R26.1 R105.2 R106.1 R114.1 SH19.1 TP2.1(Pin1) U7.C5(VDD1) U7.E2(VOUT33) U7.E4(VDD3) U7.F4(VDDA) U7.G4(VREFH) U7.G7(VDD2) U7.H5(VBAT) U8.4(~{2OE}) U8.14(VCC)
VCC: C19.1 C25.1 C26.1 C27.1 C36.1 C42.1 C43.1 D4.A(ANODE) D8.A(ANODE) D12.A(ANODE) J14.1(A1) R5.2 R25.2 R53.1 R54.1 R113.1 R556.1 SH19.2 TP4.1(Pin1) U1.1(VREFH) U1.19(VDD) U1.35(VBAT2) U1.43(VBAT1) U1.55(VDD) U1.56(VDDA)
DIO0: SH40.1 TP49.1(Pin1) U1.49(DIO0/PTE2)
DIO1: SH41.1 TP47.1(Pin1) U1.50(DIO1/PTE3)
DIO4: SH46.1 TP43.1(Pin1) U1.53(DIO4)
DIO5/CLKOUT: SH45.1 TP42.1(Pin1) U1.54(DIO5/CLKOUT)
EXTAL0: C23.2 U7.H8(PTA18/EXTAL0/FTM0_FLT2/FTM_CLKIN0) X1.1
EXTAL_32M: C21.1 U1.46(XTA) Y1.1
JTAG_TCLK_K22F: J13.4(B2) TP509.1(Pin1) U7.D3(PTA0/JTAG_TCLK/SWD_CLK/EZP_CLK/~{UART0_CTS}/FTM0_CH5)
JTAG_TDI_K22F: J13.8(B4) TP511.1(Pin1) U7.D4(PTA1/JTAG_TDI/EZP_DI/UART0_RX/FTM0_CH6)
JTAG_TDO_K22F: J13.6(B3) TP510.1(Pin1) U7.E5(PTA2/JTAG_TDO/TRACE_SWO/EZP_DO/UART0_TX/FTM0_CH7)
JTAG_TMS_K22F: J13.2(B1) R26.2 TP508.1(Pin1) U7.D5(PTA3/JTAG_TMS/SWD_DIO/~{UART0_RTS}/FTM0_CH0)
PTA0/SWD_CLK: SH47.2 TP36.1(Pin1) U1.10(PTA0/SWD_CLK)
PTA1/UART0_RX: R89.2 TP113.1(Pin1) U1.14(PTA1/DISABLED)
PTA2/UART0_TX: R88.1 TP114.1(Pin1) U1.13(PTA2/DISABLED)
PTA3/SWD_DIO: J14.2(B1) R25.1 R92.2 TP32.1(Pin1) U1.11(PTA3/SWD_DIO)
PTA12_K22F/LED: R30.2 U7.H6(PTA12/FTM1_CH0/I2S0_TXD0/FTM1_QD_PHA)
PTA13_K22F/SW: SW2.1 TP30.1(Pin1) U7.G6(PTA13/LLWU_P4/FTM1_CH1/I2S0_TX_FS/FTM1_QD_PHB)
PTA18: SH45.2 U1.15(PTA18/EXTAL0)
PTA19: SH46.2 U1.16(PTA19/XTAL0)
PTB0: R31.2 U1.17(PTB0)
PTB2: R91.2 TP117.1(Pin1) U1.21(PTB2)
PTB17: R90.2 TP116.1(Pin1) U1.22(PTB17)
PTC1: U1.24(PTC1/ADC0_SE15) U7.B4(PTC10/ADC1_SE6b/I2C1_SCL/FTM3_CH6/I2S0_RX_FS/FB_AD5)
PTC2: U1.25(PTC2/ADC0_SE11) U7.A5(PTC11/LLWU_P11/ADC1_SE7b/I2C1_SDA/FTM3_CH7/~{FB_RW})
PTC3: SH40.2 U1.26(PTC3)
PTC4: SH41.2 U1.23(PTC4/DISABLED)
PTD4_SPI1_PCS0: U1.27(PTD4) U7.C3(PTD0/LLWU_P12/SPI0_PCS0/~{UART2_RTS}/FTM3_CH0/FB_ALE/~{FB_CS1}/~{FB_TS}/~{LPUART0_RTS})
PTD5_SPI1_SCK: U1.28(PTD5) U7.A4(PTD1/ADC0_SE5b/SPI0_SCK/~{UART2_CTS}/FTM3_CH1/~{FB_CS0}/~{LPUART0_CTS})
PTD6: C51.1 R556.2 SW1.1 TP23.1(Pin1) U1.29(PTD6)
PTE0_SPI1_MISO: U1.32(PTE0/DISABLED) U7.B6(PTC7/CMP0_IN1/SPI0_SIN/USB_SOF_OUT/I2S0_RX_FS/FB_AD8)
PTE1_SPI1_MOSI: U1.34(PTE1) U7.A7(PTC6/LLWU_P10/CMP0_IN0/SPI0_SOUT/PDB0_EXTRG/I2S0_RX_BCLK/FB_AD9/I2S0_MCLK)
PTE18_I2C0_SDA: R11.2 R53.2 U7.B3(PTD3/SPI0_SIN/UART2_TX/FTM3_CH3/FB_AD3/LPUART0_TX/I2C0_SDA)
PTE19_I2C0_SCL: R15.1 R54.2 U7.C2(PTD2/LLWU_P13/SPI0_SOUT/UART2_RX/FTM3_CH2/FB_AD4/LPUART0_RX/I2C0_SCL)
PTE30: R85.1 U1.9(PTE30/DAC_OUT/ADC0_SE23/CMP0_IN4)
r_SWD_DIO_TGTMCU: R92.1 U8.3(1Y) U8.9(3A)
RESET_B_TGTMCU: R14.1 R17.2 U7.A8(PTC5/LLWU_P9/SPI0_SCK/LPTMR0_ALT2/I2S0_RXD0/FB_AD10/CMP0_OUT/FTM0_CH2)
RESET_B_XCVR: R5.1 SH44.2 U1.48(RESET)
RESET_TGTMCU_B: C60.1 J14.10(B5) R14.2 R113.2 SW5.2 TP35.1(Pin1) U1.33(PTA20/RESET_b)
RFIO: L9.1 U1.39(RFIO)
RFIO_EXT: C4.1 C7.1 C50.1 C58.1 L2.2
RST_K22F: C62.1 J13.10(B5) R114.2 SW6.2 TP105.1(Pin1) TP512.1(Pin1) U7.F8(~{RESET})
SDA_SPI0_SCK: U7.C1(PTD5/ADC0_SE6b/SPI0_PCS2/~{UART0_CTS}/FTM0_CH5/FB_AD1/~{EWM_OUT}/SPI1_SCK) U8.12(4A)
SDA_SPI0_SIN: R112.1 U7.A2(PTD7/UART0_TX/FTM0_CH7/FTM0_FLT1/SPI1_SIN) U8.8(3Y)
SDA_SPI0_SOUT: U7.B2(PTD6/LLWU_P15/ADC0_SE7b/SPI0_PCS3/UART0_RX/FTM0_CH6/FB_AD0/FTM0_FLT0/SPI1_SOUT) U8.2(1A)
SDA_SWD_EN: R106.2 U7.G5(PTA4/LLWU_P3/~{NMI}/~{EZP_CS}/FTM0_CH1) U8.10(~{3OE}) U8.13(~{4OE})
SDA_SWD_OE_B: R105.1 U7.A3(PTD4/LLWU_P14/SPI0_PCS1/~{UART0_RTS}/FTM0_CH4/FB_AD2/EWM_IN/SPI1_PCS0) U8.1(~{1OE})
SWD_CLK_TGTMCU: J14.4(B2) R93.2 SH47.1 TP51.1(Pin1)
UART1_CTS_TGTMCU: R90.1 U7.C6(PTC1/LLWU_P6/ADC0_SE15/SPI0_PCS3/~{UART1_RTS}/FTM0_CH0/FB_AD13/I2S0_TXD0/~{LPUART0_RTS})
UART1_RTS_TGTMCU: R91.1 U7.B7(PTC2/ADC0_SE4b/CMP1_IN0/SPI0_PCS2/~{UART1_CTS}/FTM0_CH1/FB_AD12/I2S0_TX_FS/~{LPUART0_CTS})
UART1_RX_TGTMCU: R89.1 U7.B8(PTC4/LLWU_P8/SPI0_PCS0/UART1_TX/FTM0_CH3/FB_AD11/CMP1_OUT/LPUART0_TX)
UART1_TX_TGTMCU: R88.2 U7.C8(PTC3/LLWU_P7/CMP1_IN1/SPI0_PCS1/UART1_RX/FTM0_CH2/CLKOUT/I2S0_TX_BCLK/LPUART0_RX)
USBDM: C38.1 R50.2 TP22.1(Pin1) U7.D1(USB0_DM)
USBDP: C37.1 R51.2 TP25.1(Pin1) U7.E1(USB0_DP)
VR_ANA: C44.1 TP46.1(Pin1) U1.44(VR_ANA)
VR_DIG: C28.1 TP48.1(Pin1) U1.45(VR_DIG)
VR_PA: C14.1 C16.1 L11.1 U1.42(VR_PA)
VUSB: C49.1 D18.C TP104.1(Pin1) U7.D2(VREGIN)
XTAL0: C24.2 U7.G8(PTA19/XTAL0/FTM1_FLT0/FTM_CLKIN1/LPTMR0_ALT1) X1.3
XTAL_32M: C22.1 U1.47(XTB) Y1.3
N23869826: TP37.1(Pin1) U1.37(RXTX)
N23870337: C13.1 C15.1 L9.2 L11.2
N23870339: C11.2 C13.2 C46.1 L5.1
N23870349: C7.2 C9.1 C11.1 L2.1 L5.2
N23913269: R85.2 SH44.1
N23948926: C58.2 J49.1(CENTER)
N23974000: D12.C(CATHODE) R31.1 TP21.1(Pin1)
N24026304: C17.1 C50.2 L3.1
N24026588: ANT1.2(Feed) C20.1 L3.2
N24037103: R11.1 U1.7(PTE18/ADC0_DP2/ADC0_SE2)
N24037421: R15.2 U1.8(PTE19/ADC0_DM2/ADC0_SE6a)
N24069474: TP24.1(Pin1) U1.6(PTE17/ADC0_DM1/ADC0_SE5a)
N24071066: TP44.1(Pin1) U1.51(DIO2)
N24071069: TP45.1(Pin1) U1.52(DIO3)
N24103085: J5.A1(VCC) L6.1 TVS1.1(A1)
N24103119: J5.S1(SGND1) J5.S2(SGND2) L7.1
N24103131: J5.A2(DATA+) R50.1 TVS3.1(A1)
N24103151: J5.A3(DATA-) R51.1 TVS2.1(A1)
N24103276: D18.A L6.2
N24103280: D8.C(CATHODE) R30.1 TP17.1(Pin1)
N24103316: D4.C(CATHODE) R10.1 TP8.1(Pin1)
N24103468: TP102.1(Pin1) U7.A1(PTE0/CLKOUT32K/ADC1_SE4a/SPI1_PCS1/UART1_TX/I2C1_SDA/RTC_CLKOUT)
N24109842: R93.1 U8.11(4Y)

Not connected (* = marked no-connect by the designer): J13 7(A4)* 9(A5)*; J14 6(B3)* 7(A4)* 8(B4)* 9(A5)*; U1 5(PTE16/ADC0DP1/ADC0_SE1)* 12(PTA4/NMI_b)* 18(PTB1)* 30(NC)* 31(PTD7)* 41(PA_BOOST)* 57(MISO/PTC7)* 58(NSS/PTD0)* 59(SCK/PTC5)* 60(MOSI/PTC6)*; U7 A6(PTC8/ADC1_SE4b/CMP0_IN2/FTM3_CH4/I2S0_MCLK/FB_AD7)* B1(PTE1/LLWU_P0/ADC1_SE5a/SPI1_SOUT/UART1_RX/I2C1_SCL/SPI1_SIN)* B5(PTC9/ADC1_SE5b/CMP0_IN3/FTM3_CH5/I2S0_RX_BCLK/FB_AD6/FTM2_FLT0)* C7(PTB19/FTM2_CH1/I2S0_TX_FS/~{FB_OE}/FTM2_QD_PHB)* D6(PTB18/FTM2_CH0/I2S0_TX_BCLK/FB_AD15/FTM2_QD_PHA)* D7(PTB17/SPI1_SIN/UART0_TX/FTM_CLKIN1/FB_AD16/~{EWM_OUT})* D8(PTC0/ADC0_SE14/SPI0_PCS4/PDB0_EXTRG/USB_SOF_OUT/FB_AD14)* E6(PTB16/SPI1_SOUT/UART0_RX/FTM_CLKIN0/FB_AD17/EWM_IN)* E7(PTB2/ADC0_SE12/I2C0_SCL/~{UART0_RTS}/FTM0_FLT3)* E8(PTB3/ADC0_SE13/I2C0_SDA/~{UART0_CTS}/FTM0_FLT0)* F1(ADC0_DM0/ADC1_DM3)* F2(ADC1_DM0/ADC0_DM3)* F5(PTA5/USB_CLKIN/FTM0_CH2/I2S0_TX_BCLK/~{JTAG_TRST})* F6(PTB1/ADC0_SE9/ADC1_SE9/I2C0_SDA/FTM1_CH1/FTM1_QD_PHB)* F7(PTB0/LLWU_P5/ADC0_SE8/ADC1_SE8/I2C0_SCL/FTM1_CH0/FTM1_QD_PHA)* G1(ADC0_DP0/ADC1_DP3)* G2(ADC1_DP0/ADC0_DP3)* H1(VREF_OUT/CMP1_IN5/CMP0_IN5/ADC1_SE18)* H2(DAC0_OUT/CMP1_IN3/ADC0_SE23)* H3(XTAL32)* H4(EXTAL32)*; U8 5(2A)* 6(2Y)*

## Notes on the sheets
sheet 1
- Table of Contents
- Revisions
- 2
- NOTES
- Rev
- Description
- Date
- Approved
- 3
- Block Diagram
- A
- Initial Release
- 6/25/2015
- 4
- K22F USB and OpenSDA
- 5
- KW01 MICROCONTROLLER
- USB-KW019032
- SCH-28746
sheet 2
- TODO: UPDATE REFDES and NOTES
  1. Unless Otherwise Specified:
- All resistors are in ohms, 5%, 1/8 Watt
- All capacitors are in uF, 20%, 50V
- All voltages are DC
- All polarized capacitors are aluminum electrolytic
- 2. Interrupted lines coded with the same letter or letter
      combinations are electrically connected.
- 3. Device type number is for reference only. The number
      varies with the manufacturer.
- 4. Special signal usage:
- _B Denotes - Active-Low Signal
- <> or [] Denotes - Vectored Signals
- 5. Interpret diagram in accordance with American
  National Standards Institute specifications, current
  revision, with the exception of logic block symbology.
- SCH-28746
sheet 3
- SCH-28746
sheet 4
- USB
- SERIAL RX/TX
  POKA-YOKE:
  Place both
  resistors
  with the same orientation
  and provide same airgap
  between RX to TX resistors
  terminals in a square fashion.
- TX
- TX
- RX
- RX
- CAD NOTE: These capacitors must be placed
                       as close to MCU as possible
- POWER
  ENABLE
  KW01
- CAD Note:
  Silkscreen "MCU"
- PUSH BUTTON
- LEDs
- CAD Note:
  Silkscreen
  "RESET"
- RESET
- PIN FUNCTIONS USED
- NET NAMES
- 8MHz XTAL
- JTAG/SWD CONNECTOR K22FN512VMP12
- OpenSDA
- SCH-28746
sheet 5
- RXD1
- SWD_CLK
- TXD1
- SWD_DIO
- CAD Note:
  Place TP42
  close to pin 54
- Capacitors
  share pin 1
- SERIAL RX/TX
  POKA-YOKE:
  Place both
  resistors
  with the same orientation
  and provide same airgap
  between RX to TX resistors
  terminals in a square fashion.
- TX
- TX
- RX
- RX
- CAD Note:
  Silkscreen
  "RESET"
- XTAL_32M
- RESET
- CAD Note: Cut traces on bottom side
- CAD Note:
  Silkscreen "KW01"
- JTAG / SWD
- CAD Note:
  Board shall be 100% testable
- PIN FUNCTIONS USED
- SWD_CLK
- PTA20
- Cut trace to isolate the
  MCU from the OpenSDA
  debug interface
- CAD Placement Note:
  Mating 10-pin connector may be plugged into
  both JTAG connectors at one time
- SCH-28746
